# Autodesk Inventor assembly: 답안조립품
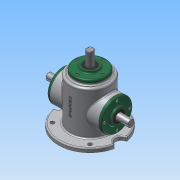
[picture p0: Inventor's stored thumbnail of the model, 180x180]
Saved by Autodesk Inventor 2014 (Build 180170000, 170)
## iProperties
Created: 2018-04
Part Number: 답안조립품
Document SubType Name: Assembly
Designer: 703
Author: 703
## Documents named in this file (16)
- C:\Users\user\Desktop\480407V1001\답안조립품.iam
- C:\Users\user\Desktop\480407V1001\본체.ipt
- C:\Users\user\Desktop\480407V1001\메인 베벨기어.ipt
- C:\Users\user\Desktop\480407V1001\메인 축.ipt
- 메인 축.ipt
- C:\Users\user\Desktop\480407V1001\베어링 6203.ipt
- C:\Users\user\Desktop\480407V1001\볼트 M4.ipt
- 볼트 M4.ipt
- C:\Users\user\Desktop\480407V1001\서브 베벨기어.ipt
- C:\Users\user\Desktop\480407V1001\서브 축.ipt
- 서브 축.ipt
- C:\Users\user\Desktop\480407V1001\오일 실.ipt
- 오일 실.ipt
- C:\Users\user\Desktop\480407V1001\커버.ipt
- C:\Users\user\Desktop\480407V1001\키 4x4.ipt
- C:\Users\user\Desktop\480407V1001\키 5x5.ipt
